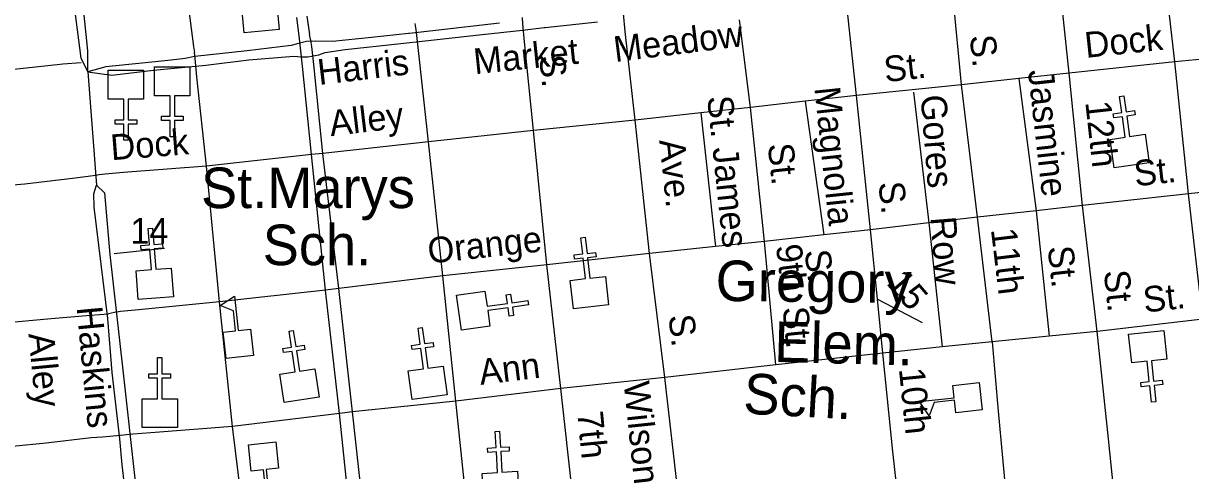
# Model space of a CAD drawing. Extents: x 2290055 to 2389491, y 66597 to 237875.
# Drawn here: x 2318340 to 2322658, y 176940 to 178595 of the extents above; entities that cross this region are included whole.
import ezdxf

# ---------------------------------------------------------------- set-up
doc = ezdxf.new("R2010")
doc.units = 0
for name, color, linetype in [('Exist Cultural Church CELL', 7, 'Continuous'), ('Exist Cultural Educational Facility Elementary CELL', 7, 'Continuous'), ('Exist Cultural Educational Facility Elementary Label', 7, 'Continuous'), ('Exist Road Non-System Type 51', 7, 'Continuous'), ('Exist Road Non-System Type 51 Label', 7, 'Continuous'), ('Exist Road Primary US Divided Attributed', 7, 'Continuous'), ('Exist Road Primary US Label', 7, 'Continuous'), ('Exist Road Primary US UnDivided 4 Lane Attributed', 7, 'Continuous'), ('Exist Road Secondary Type 51 Divided Attributed', 7, 'Continuous')]:
    doc.layers.add(name, color=color, linetype=linetype)

msp = doc.modelspace()

# ---------------------------------------------------------------- linework, layer by layer
at = {"layer": 'Exist Cultural Church CELL'}
for points in [[(2319146.8, 178665.7), (2319203.5, 178670.9), (2319196.6, 178746.8), (2319164.8, 178743.9), (2319163.3, 178759.8), (2319195.2, 178762.7), (2319189.7, 178822.6), (2319205.7, 178824), (2319211.1, 178764.1), (2319243, 178767), (2319244.5, 178751.1), (2319212.6, 178748.2), (2319219.5, 178672.4), (2319276.9, 178677.5), (2319286.6, 178571.5), (2319156.5, 178559.6)], [(2318784.4, 178314.4), (2318727.5, 178314.3), (2318727.5, 178238.1), (2318759.5, 178238.1), (2318759.5, 178222.2), (2318727.5, 178222.2), (2318727.5, 178162), (2318711.4, 178162), (2318711.4, 178222.2), (2318679.4, 178222.2), (2318679.4, 178238.1), (2318711.4, 178238.1), (2318711.4, 178314.3), (2318653.8, 178314.4), (2318653.8, 178420.9), (2318784.4, 178420.9)], [(2318956.3, 178327), (2318899.3, 178326.9), (2318899.3, 178250.7), (2318931.3, 178250.7), (2318931.3, 178234.8), (2318899.3, 178234.8), (2318899.3, 178174.6), (2318883.3, 178174.6), (2318883.3, 178234.8), (2318851.3, 178234.8), (2318851.3, 178250.7), (2318883.3, 178250.7), (2318883.3, 178326.9), (2318825.7, 178327), (2318825.7, 178433.4), (2318956.3, 178433.4)], [(2322360, 178165.5), (2322416.3, 178173.7), (2322405.5, 178249), (2322373.9, 178244.5), (2322371.6, 178260.3), (2322403.3, 178264.8), (2322394.8, 178324.4), (2322410.6, 178326.6), (2322419.1, 178267.1), (2322450.8, 178271.6), (2322453.1, 178255.8), (2322421.4, 178251.3), (2322432.2, 178175.9), (2322489.3, 178184), (2322504.3, 178078.6), (2322375, 178060.1)], [(2318756.9, 177679.3), (2318813.6, 177683.7), (2318807.8, 177759.7), (2318775.9, 177757.2), (2318774.6, 177773.1), (2318806.5, 177775.6), (2318801.9, 177835.6), (2318817.9, 177836.8), (2318822.5, 177776.8), (2318854.4, 177779.3), (2318855.7, 177763.4), (2318823.7, 177760.9), (2318829.6, 177685), (2318887.1, 177689.3), (2318895.3, 177583.2), (2318765, 177573.1)], [(2320363.3, 177643.6), (2320419.9, 177650.2), (2320411.2, 177725.9), (2320379.4, 177722.2), (2320377.6, 177738.1), (2320409.4, 177741.7), (2320402.6, 177801.5), (2320418.5, 177803.3), (2320425.3, 177743.5), (2320457.1, 177747.2), (2320458.9, 177731.3), (2320427.1, 177727.7), (2320435.8, 177652), (2320493.1, 177658.5), (2320505.2, 177552.7), (2320375.4, 177537.9)], [(2320047.5, 177604.1), (2320055.6, 177547.8), (2320131, 177558.5), (2320126.5, 177590.2), (2320142.3, 177592.5), (2320146.8, 177560.8), (2320206.3, 177569.3), (2320208.6, 177553.4), (2320149.1, 177544.9), (2320153.6, 177513.3), (2320137.8, 177511), (2320133.3, 177542.7), (2320057.9, 177531.9), (2320065.9, 177474.8), (2319960.5, 177459.8), (2319942.1, 177589.1)], [(2319763.8, 177308.7), (2319820.3, 177316.3), (2319810.2, 177391.8), (2319778.4, 177387.5), (2319776.3, 177403.4), (2319808, 177407.6), (2319800.1, 177467.2), (2319815.9, 177469.4), (2319823.9, 177409.8), (2319855.6, 177414), (2319857.8, 177398.2), (2319826, 177393.9), (2319836.1, 177318.5), (2319893.3, 177326), (2319907.4, 177220.5), (2319778, 177203.1)], [(2319289.1, 177297.3), (2319345.4, 177305.8), (2319334.2, 177381.1), (2319302.5, 177376.4), (2319300.2, 177392.2), (2319331.8, 177396.9), (2319323, 177456.4), (2319338.8, 177458.7), (2319347.7, 177399.2), (2319379.3, 177403.9), (2319381.7, 177388.1), (2319350, 177383.4), (2319361.2, 177308.1), (2319418.3, 177316.5), (2319433.9, 177211.2), (2319304.7, 177192)], [(2322569.8, 177352.6), (2322513.1, 177346.5), (2322521.1, 177270.8), (2322552.9, 177274.1), (2322554.6, 177258.3), (2322522.8, 177254.9), (2322529.1, 177195.1), (2322513.2, 177193.4), (2322506.9, 177253.2), (2322475, 177249.9), (2322473.4, 177265.8), (2322505.2, 177269.1), (2322497.2, 177344.8), (2322439.9, 177338.9), (2322428.7, 177444.8), (2322558.6, 177458.5)], [(2318779.7, 177206), (2318836.6, 177206.1), (2318836.6, 177282.3), (2318804.6, 177282.3), (2318804.6, 177298.3), (2318836.6, 177298.3), (2318836.6, 177358.4), (2318852.7, 177358.4), (2318852.7, 177298.3), (2318884.7, 177298.3), (2318884.7, 177282.3), (2318852.7, 177282.3), (2318852.7, 177206.1), (2318910.3, 177206), (2318910.3, 177099.6), (2318779.7, 177099.6)], [(2320037.5, 176929.9), (2320094.3, 176933.3), (2320089.9, 177009.3), (2320057.9, 177007.4), (2320057, 177023.4), (2320088.9, 177025.3), (2320085.4, 177085.3), (2320101.4, 177086.2), (2320104.9, 177026.2), (2320136.9, 177028.1), (2320137.8, 177012.1), (2320105.9, 177010.3), (2320110.3, 176934.3), (2320167.9, 176937.5), (2320174.2, 176831.3), (2320043.8, 176823.6)]]:
    msp.add_lwpolyline(points, close=True, dxfattribs=at)
at = {"layer": 'Exist Cultural Educational Facility Elementary CELL'}
for points in [[(2319089.8, 177354.8), (2319079.5, 177452.2), (2319125.3, 177457), (2319117.5, 177531.7), (2319068.1, 177550.9), (2319121.4, 177585.8), (2319134.9, 177458), (2319180.6, 177462.8), (2319190.9, 177365.5)], [(2321886.5, 177164.7), (2321789.1, 177154.4), (2321784.3, 177200.2), (2321709.6, 177192.3), (2321690.5, 177143), (2321655.5, 177196.3), (2321783.3, 177209.8), (2321778.5, 177255.5), (2321875.9, 177265.8)], [(2319273.7, 177046), (2319283.9, 176948.6), (2319238.1, 176943.8), (2319246, 176869.1), (2319295.3, 176849.9), (2319242, 176815), (2319228.6, 176942.8), (2319182.8, 176938), (2319172.5, 177035.3)]]:
    msp.add_lwpolyline(points, close=True, dxfattribs=at)
at = {"layer": 'Exist Road Non-System Type 51'}
for p, q in [((2318921.3, 178878.4), (2318961.2, 178575.9)), ((2322599.5, 178452), (2322562.6, 178777.6)), ((2322208.9, 178410.6), (2322174, 178734.9)), ((2321810.6, 178366.6), (2321778.7, 178695.1)), ((2321422, 178327.2), (2321387.2, 178649.1)), ((2319360.3, 178548.7), (2319351.7, 178615.7)), ((2319389.1, 178620.7), (2319398.3, 178553.6)), ((2319792.8, 178572.1), (2319789.7, 178594.4)), ((2320187.2, 178593.2), (2320187, 178615.8)), ((2321029.5, 178283.8), (2320989.4, 178607.6)), ((2318961.2, 178575.9), (2318970.1, 178508.4)), ((2319403.1, 178531.5), (2319398.3, 178553.6)), ((2319796, 178549.7), (2319792.8, 178572.1)), ((2319803.4, 178482.5), (2319796, 178549.7)), ((2320603.1, 178236.7), (2320566.5, 178564.1)), ((2318970.1, 178508.4), (2318972.9, 178486.6)), ((2319365.5, 178504), (2319363.2, 178526)), ((2319406.8, 178509), (2319403.1, 178531.5)), ((2319414.3, 178442), (2319406.8, 178509)), ((2320226.6, 178197.9), (2320193.3, 178525.7)), ((2318975.3, 178463.9), (2318972.9, 178486.6)), ((2318982.4, 178396.9), (2318975.3, 178463.9)), ((2319372.4, 178436.3), (2319365.5, 178504)), ((2319838.3, 178156.6), (2319803.4, 178482.5)), ((2322994.1, 178489.6), (2322599.5, 178452)), ((2318553.8, 178449), (2318486.3, 178443.5)), ((2319406, 178109.6), (2319372.4, 178436.3)), ((2319447.8, 178113.2), (2319414.3, 178442)), ((2322599.5, 178452), (2322208.9, 178410.6)), ((2322650.7, 177963.7), (2322599.5, 178452)), ((2319017.5, 178066), (2318982.4, 178396.9)), ((2322023.1, 178390.1), (2321810.6, 178366.6)), ((2322208.9, 178410.6), (2322023.1, 178390.1)), ((2322258.2, 177920.2), (2322208.9, 178410.6)), ((2321810.6, 178366.6), (2321422, 178327.2)), ((2321870, 177877), (2321810.6, 178366.6)), ((2321232.5, 178306.3), (2321029.5, 178283.8)), ((2321422, 178327.2), (2321232.5, 178306.3)), ((2321473.4, 177831.1), (2321422, 178327.2)), ((2320845.8, 178263.5), (2320603.1, 178236.7)), ((2321029.5, 178283.8), (2320845.8, 178263.5)), ((2321081.3, 177787.7), (2321029.5, 178283.8)), ((2320603.1, 178236.7), (2320226.6, 178197.9)), ((2320656.8, 177743), (2320603.1, 178236.7)), ((2320226.6, 178197.9), (2319838.3, 178156.6)), ((2320276.4, 177701.6), (2320226.6, 178197.9)), ((2319838.3, 178156.6), (2319447.8, 178113.2)), ((2319891.8, 177660.5), (2319838.3, 178156.6)), ((2319406, 178109.6), (2319017.5, 178066)), ((2319447.8, 178113.2), (2319406, 178109.6)), ((2319457.7, 177607.2), (2319406, 178109.6)), ((2319507.7, 177613.5), (2319447.8, 178113.2)), ((2318598.4, 178030.2), (2318531.3, 178021.4)), ((2318620.7, 178034.2), (2318598.4, 178030.2)), ((2318643.1, 178036.6), (2318620.7, 178034.2)), ((2318710.5, 178042.2), (2318643.1, 178036.6)), ((2319017.5, 178066), (2318710.5, 178042.2)), ((2319065.3, 177563.8), (2319017.5, 178066)), ((2322876, 177988.6), (2322650.7, 177963.7)), ((2322650.7, 177963.7), (2322258.2, 177920.2)), ((2322703.2, 177499.7), (2322650.7, 177963.7)), ((2322086.2, 177901.1), (2321870, 177877)), ((2322258.2, 177920.2), (2322086.2, 177901.1)), ((2322312.8, 177454.4), (2322258.2, 177920.2)), ((2321870, 177877), (2321690.1, 177856.2)), ((2321924, 177417), (2321870, 177877)), ((2321473.4, 177831.1), (2321301.7, 177812.1)), ((2321690.1, 177856.2), (2321473.4, 177831.1)), ((2321499.4, 177574.8), (2321473.4, 177831.1)), ((2321081.3, 177787.7), (2320901, 177768.7)), ((2321301.7, 177812.1), (2321081.3, 177787.7)), ((2321123.4, 177331.2), (2321081.3, 177787.7)), ((2320656.8, 177743), (2320276.4, 177701.6)), ((2320901, 177768.7), (2320656.8, 177743)), ((2320713, 177285.1), (2320656.8, 177743)), ((2320276.4, 177701.6), (2319891.8, 177660.5)), ((2320328.3, 177243.6), (2320276.4, 177701.6)), ((2319891.8, 177660.5), (2319507.7, 177613.5)), ((2319940.3, 177196.4), (2319891.8, 177660.5)), ((2319457.7, 177607.2), (2319065.3, 177563.8)), ((2319507.7, 177613.5), (2319457.7, 177607.2)), ((2319509.9, 177151.1), (2319457.7, 177607.2)), ((2319557.6, 177157.3), (2319507.7, 177613.5)), ((2319113.7, 177103.6), (2319065.3, 177563.8)), ((2321519.7, 177374.8), (2321499.4, 177574.8)), ((2318587.9, 177514.6), (2318655.4, 177520.6)), ((2318677.6, 177524.6), (2318655.4, 177520.6)), ((2318699.9, 177528.6), (2318677.6, 177524.6)), ((2318767.2, 177535.4), (2318699.9, 177528.6)), ((2322703.2, 177499.7), (2322312.8, 177454.4)), ((2322134.2, 177437.2), (2321924, 177417)), ((2322312.8, 177454.4), (2322134.2, 177437.2)), ((2321739.4, 177397.7), (2321519.7, 177374.8)), ((2321924, 177417), (2321739.4, 177397.7)), ((2321519.7, 177374.8), (2321123.4, 177331.2)), ((2321123.4, 177331.2), (2320713, 177285.1)), ((2320713, 177285.1), (2320328.3, 177243.6)), ((2320765.3, 176824.7), (2320713, 177285.1)), ((2320328.3, 177243.6), (2319940.3, 177196.4)), ((2320378.6, 176785.5), (2320328.3, 177243.6)), ((2319940.3, 177196.4), (2319557.6, 177157.3)), ((2319988.2, 176742.1), (2319940.3, 177196.4)), ((2319509.9, 177151.1), (2319113.7, 177103.6)), ((2319557.6, 177157.3), (2319509.9, 177151.1)), ((2319558, 176689), (2319509.9, 177151.1)), ((2319607.9, 176699.2), (2319557.6, 177157.3)), ((2319113.7, 177103.6), (2318812, 177080)), ((2319169.9, 176643.7), (2319113.7, 177103.6)), ((2318699.7, 177069.5), (2318632.3, 177064.1)), ((2318722.2, 177072), (2318699.7, 177069.5)), ((2318744.6, 177074.5), (2318722.2, 177072)), ((2318812, 177080), (2318744.6, 177074.5))]:
    msp.add_line(p, q, dxfattribs=at)
for points in [[(2320193.3, 178525.7), (2320187.2, 178593.1), (2320187.2, 178593.2)], [(2320566.5, 178564.1), (2320559.8, 178631.3), (2320559.8, 178631.4)], [(2319363.2, 178526), (2319360.4, 178548.4), (2319360.3, 178548.7)], [(2318486.3, 178443.5), (2318476.5, 178442.7), (2318305.3, 178424.1), (2318149.8, 178403.8)], [(2322023.1, 178390.1), (2322086.2, 177901.1)], [(2321632.8, 178340.2), (2321690.1, 177856.2)], [(2321232.5, 178306.3), (2321301.7, 177812.1)], [(2320845.8, 178263.5), (2320901, 177768.7)], [(2318531.3, 178021.4), (2318501.2, 178017.7), (2318346, 177999.4), (2318198.5, 177987.6)], [(2322086.2, 177901.1), (2322134.2, 177437.2)], [(2321690.1, 177856.2), (2321739.4, 177397.7)], [(2318675.9, 177743.2), (2318862.4, 177763.2)], [(2319065.3, 177563.8), (2318767.2, 177535.4), (2318767.2, 177535.4)], [(2321499.4, 177574.8), (2321664.5, 177488.1)], [(2318254.1, 177485.7), (2318443.5, 177503.1), (2318587.9, 177514.6)], [(2322455.2, 176077.4), (2322428.8, 176338.6), (2322396.5, 176649.4), (2322354.4, 177058), (2322312.8, 177454.4)], [(2321924, 177417), (2321946.4, 177159.6), (2321978.1, 176815), (2322025, 176432.5), (2322047.9, 176211.6), (2322070.8, 176038.2)], [(2321668.2, 175994.4), (2321646.1, 176205.5), (2321599.3, 176623.7), (2321556.1, 177010.3), (2321519.7, 177374.8)], [(2318632.3, 177064.1), (2318591.2, 177060.9), (2318424, 177042.2), (2318300.4, 177029.4)]]:
    msp.add_lwpolyline(points, dxfattribs=at)
at = {"layer": 'Exist Road Primary US Divided Attributed'}
for points in [[(2318578.5, 178415.1), (2318667, 178403), (2318821.7, 178421.1), (2319015.5, 178439.9), (2319174.5, 178459.6), (2319340.7, 178473.6), (2319367.2, 178470.8), (2319392.8, 178471.2), (2319432.9, 178478.4), (2319457, 178487.3), (2319530.4, 178497.7), (2319736.1, 178520.5), (2319825.9, 178530.2), (2320036.9, 178553.4), (2320186.5, 178569.4), (2320266.7, 178578.9), (2320269.9, 178579.3), (2320463.4, 178600.3)], [(2320101.1, 178595.6), (2319865.6, 178568.4), (2319767.4, 178557.3), (2319765.3, 178557), (2319627.8, 178542.8), (2319484.3, 178527.5), (2319421.7, 178528.1), (2319387.6, 178527.3), (2319349.1, 178517.7), (2319331.1, 178512.9), (2319167.5, 178492.8), (2318974.5, 178471.6), (2318938.6, 178464.4), (2318886.9, 178458), (2318779.4, 178446.7), (2318645.5, 178433.9), (2318578.5, 178415.1)], [(2318954, 174746.3), (2318925.8, 174933), (2318905.4, 175146.1), (2318882.8, 175393.3), (2318857.6, 175663.5), (2318838.9, 175801.6), (2318803.5, 176117.8), (2318766.4, 176430.7), (2318749, 176592.6), (2318705.1, 176960.9), (2318697, 177057.2), (2318668.8, 177303.5), (2318653.1, 177503), (2318602.4, 177914.7), (2318601.1, 177963.3), (2318610.4, 177996.5)], [(2318610.4, 177996.5), (2318640.7, 177967.5), (2318659.5, 177740), (2318708, 177312.1), (2318756.6, 176877.3), (2318809.5, 176330.1), (2318859.8, 175897.1), (2318886.2, 175667.8), (2318915.2, 175378), (2318928, 175243.3), (2318949.3, 175055.8), (2318995.3, 174748)]]:
    msp.add_lwpolyline(points, dxfattribs=at)
at = {"layer": 'Exist Road Primary US UnDivided 4 Lane Attributed'}
msp.add_line((2318578.5, 178415.1), (2318610.4, 177996.5), dxfattribs=at)
at = {"layer": 'Exist Road Secondary Type 51 Divided Attributed'}
for points in [[(2318027.2, 183059.5), (2318035.9, 182973.4), (2318063.7, 182771.3), (2318099, 182502.1), (2318195.1, 181666.4), (2318330.6, 180493.6), (2318368.5, 180095.5), (2318464.6, 179239.8), (2318504.2, 178838.1), (2318552.9, 178465.3), (2318578.5, 178415.1)], [(2318578.5, 178415.1), (2318578.5, 178492.6), (2318455, 179699.7), (2318326.7, 180887.2), (2318240.3, 181669.1), (2318199.7, 182060.4), (2318135.2, 182503), (2318103.9, 182783.7), (2318082.6, 183062.2)]]:
    msp.add_lwpolyline(points, dxfattribs=at)

# ---------------------------------------------------------------- texts
at = {"layer": 'Exist Cultural Educational Facility Elementary Label'}
for s, p in [('St.Marys', (2318997.2, 177911.1)), ('Sch.', (2319225.4, 177700))]:
    msp.add_text(s, height=150, dxfattribs=at).set_placement(p)
for s, rotation, p in [('Gregory', 359.3452, (2320900.4, 177567.8)), ('Elem.', 358.5038, (2321116.4, 177342.3)), ('Sch.', 356.9272, (2321001, 177151.2))]:
    msp.add_text(s, height=150, rotation=rotation, dxfattribs=at).set_placement(p)
at = {"layer": 'Exist Road Non-System Type 51 Label'}
for s, rotation, p in [('Dock', 6.0492, (2322271, 178466.6)), ('Meadow', 7.1222, (2320529.5, 178451)), ('S.', 275.7588, (2321840.8, 178548.2)), ('Harris', 6.748, (2319434.1, 178366.5)), ('S.', 275.7985, (2320248, 178473.6)), ('St.', 6.5167, (2321528.8, 178376.7)), ('Jasmine', 276.4105, (2322056.2, 178419)), ('Magnolia', 276.0128, (2321266, 178355.8)), ('Alley', 6.748, (2319477.3, 178176.9)), ('St. James', 275.9727, (2320869.3, 178322.6)), ('Gores   Row', 274.5743, (2321658.9, 178327.1)), ('12th', 276.2607, (2322268.2, 178303.3)), ('Dock', 4.4357, (2318666, 178088.1)), ('Ave.', 275.9727, (2320692.1, 178162.1)), ('St.', 276.0128, (2321093.5, 178147)), ('St.', 6.3153, (2322453.7, 177991.4)), ('S.', 276.1735, (2321502.8, 178005)), ('Orange', 6.1065, (2319840.7, 177705.9)), ('11th', 276.7972, (2321919.1, 177832.4)), ('9th', 276.9208, (2321123.7, 177772.6)), ('S.', 276.8446, (2321229.7, 177753)), ('St.', 276.1499, (2322128.9, 177767.2)), ('15', 310.7235, (2321529.5, 177632.7)), ('St.', 275.918, (2322336.6, 177677.9)), ('St.', 6.6219, (2322487.7, 177524.2)), ('Haskins', 275.3761, (2318537, 177543.9)), ('S.', 276.4532, (2320726.2, 177513.3)), ('St.', 275.6371, (2321148.3, 177542.7)), ('Alley', 275.3761, (2318358.8, 177446.1)), ('Ann', 6.9348, (2320031.4, 177257)), ('10th', 275.8799, (2321578.8, 177316.4)), ('Wilson', 276.0235, (2320560.5, 177265)), ('7th', 275.6026, (2320388.8, 177155.8))]:
    msp.add_text(s, height=95, rotation=rotation, dxfattribs=at).set_placement(p)
msp.add_text('14', height=95, dxfattribs=at).set_placement((2318735.7, 177779.4))
at = {"layer": 'Exist Road Primary US Label'}
msp.add_text('Market', height=95, rotation=5.8821, dxfattribs=at).set_placement((2320010.3, 178406))

doc.saveas('drawing.dxf')
